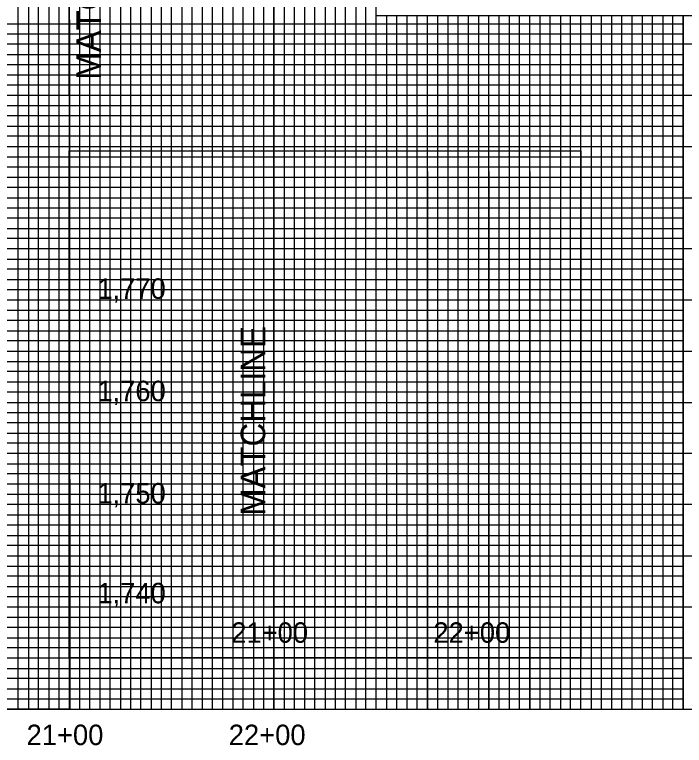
# Model space of a CAD drawing. Extents: x 505602 to 507548, y 483109 to 484209.
# Drawn here: x 506892.4 to 507219.7, y 483666.1 to 484023.2 of the extents above; entities that cross this region are included whole.
import ezdxf

# ---------------------------------------------------------------- set-up
doc = ezdxf.new("R2010")
doc.units = 0
for name, color, linetype in [('Exist Vertical Profile Vertical Axis Label', 7, 'Continuous'), ('Matchline', 7, 'Continuous'), ('Matchline Text', 7, 'Continuous'), ('Scratch_Level_5', 7, 'Continuous'), ('Sheet Layout Profile Border Port 1', 7, 'Continuous'), ('Sheet Profile CELL', 7, 'Continuous'), ('Sheet Profile Grid Major CELL', 7, 'Continuous'), ('Sheet Profile Grid Middle CELL', 7, 'Continuous'), ('Sheet Profile Grid Minor CELL', 7, 'Continuous'), ('Sheet Sticker Exception Certification CELL', 7, 'Continuous')]:
    doc.layers.add(name, color=color, linetype=linetype)

msp = doc.modelspace()

# ---------------------------------------------------------------- linework, layer by layer
at = {"layer": 'Matchline'}
for p, q in [((506919.08, 483983.71), (506919.08, 484183.71)), ((507019.08, 483750.46), (507019.08, 483883.71))]:
    msp.add_line(p, q, dxfattribs=at)
msp.add_lwpolyline([(506919.08, 483956.69), (507169.08, 483956.69), (507169.08, 483708.84), (506919.08, 483708.84)], close=True, dxfattribs=at)
at = {"layer": 'Scratch_Level_5'}
for points in [[(505819.08, 484183.83), (506824.84, 484183.83), (506824.84, 484134), (506919.08, 484133.22), (506919.3, 483683.71), (505819.08, 483683.71)], [(507019.08, 483883.71), (506919.08, 483883.71), (506919.08, 483956.69), (507119.08, 483956.69), (507119.08, 483733.71), (507019.08, 483733.71)]]:
    msp.add_lwpolyline(points, close=True, dxfattribs=at)
msp.add_lwpolyline([(505819.08, 484022.66), (505819.08, 483683.71), (507219.08, 483683.71), (507219.08, 484022.66)], dxfattribs=at)
at = {"layer": 'Sheet Layout Profile Border Port 1'}
msp.add_lwpolyline([(505819.08, 484185.09), (505819.08, 483683.71), (507019.08, 483683.71), (507019.08, 484183.71), (507019.08, 484183.71), (507019.08, 484183.71)], close=True, dxfattribs=at)
at = {"layer": 'Sheet Profile CELL'}
msp.add_line((505769.08, 483683.71), (507269.08, 483683.71), dxfattribs=at)
at = {"layer": 'Sheet Profile Grid Major CELL'}
for points in [[(506519.08, 483683.71), (506569.08, 483683.71), (506569.08, 484183.71), (506619.08, 484183.71), (506619.08, 483683.71), (506669.08, 483683.71), (506669.08, 484183.71), (506719.08, 484183.71), (506719.08, 483683.71), (506769.08, 483683.71), (506769.08, 484183.71), (506819.08, 484183.71), (506819.08, 483683.71), (506869.08, 483683.71), (506869.08, 484183.71), (506919.08, 484183.71), (506919.08, 483683.71), (506969.08, 483683.71), (506969.08, 484183.71), (507019.08, 484183.71), (507019.08, 483683.71), (507069.08, 483683.71), (507069.08, 484183.71), (507095.38, 484183.71)], [(507219.08, 484022.66), (507219.08, 483683.71), (507269.08, 483683.71), (507269.08, 484033.71)], [(507119.08, 484022.66), (507119.08, 483683.71), (507169.08, 483683.71), (507169.08, 483683.71), (507169.08, 484022.66)], [(507269.08, 483983.71), (505769.08, 483983.71), (505769.08, 483933.71), (507269.08, 483933.71)], [(507269.08, 483883.71), (505769.08, 483883.71), (505769.08, 483833.71), (507269.08, 483833.71)], [(507269.08, 483783.71), (505769.08, 483783.71), (505769.08, 483783.71), (505769.08, 483733.71), (507269.08, 483733.71)]]:
    msp.add_lwpolyline(points, dxfattribs=at)
at = {"layer": 'Sheet Profile Grid Middle CELL'}
for points in [[(506544.08, 483683.71), (506594.08, 483683.71), (506594.08, 484183.71), (506644.08, 484183.71), (506644.08, 483683.71), (506694.08, 483683.71), (506694.08, 484183.71), (506744.08, 484183.71), (506744.08, 483683.71), (506794.08, 483683.71), (506794.08, 484183.71), (506844.08, 484183.71), (506844.08, 483683.71), (506894.08, 483683.71), (506894.08, 484183.71), (506944.08, 484183.71), (506944.08, 483683.71), (506994.08, 483683.71), (506994.08, 484183.71), (507044.08, 484183.71), (507044.08, 483683.71), (507094.08, 483683.71), (507094.08, 484022.66)], [(507094.08, 483946.51), (507094.08, 483683.71), (507144.08, 483683.71), (507144.08, 484022.66)], [(507144.08, 483946.51), (507144.08, 483683.71), (507194.08, 483683.71), (507194.08, 484022.66)], [(507269.08, 484008.71), (505769.08, 484008.71), (505769.08, 483958.71), (507094.08, 483958.71)], [(507094.08, 483958.71), (507269.08, 483958.71)], [(507269.08, 483908.71), (505769.08, 483908.71), (505769.08, 483858.71), (507269.08, 483858.71)], [(507269.08, 483808.71), (505769.08, 483808.71), (505769.08, 483758.71), (507269.08, 483758.71)], [(507269.08, 483708.71), (505769.08, 483708.71)]]:
    msp.add_lwpolyline(points, dxfattribs=at)
at = {"layer": 'Sheet Profile Grid Minor CELL'}
for p, q in [((505819.08, 484018.71), (507219.08, 484018.71)), ((507219.08, 483998.71), (505819.08, 483998.71)), ((505819.08, 483993.71), (507219.08, 483993.71)), ((507219.08, 483973.71), (505819.08, 483973.71)), ((505819.08, 483968.71), (507219.08, 483968.71)), ((507219.08, 483948.71), (505819.08, 483948.71)), ((505819.08, 483943.71), (507219.08, 483943.71)), ((507219.08, 483938.71), (505819.08, 483938.71)), ((505819.08, 483928.71), (507219.08, 483928.71)), ((507219.08, 483923.71), (505819.08, 483923.71)), ((505819.08, 483918.71), (507219.08, 483918.71)), ((507219.08, 483913.71), (505819.08, 483913.71)), ((505819.08, 483903.71), (507219.08, 483903.71)), ((507219.08, 483898.71), (505819.08, 483898.71)), ((505819.08, 483893.71), (507219.08, 483893.71)), ((507219.08, 483888.71), (505819.08, 483888.71)), ((505819.08, 483878.71), (507219.08, 483878.71)), ((507219.08, 483873.71), (505819.08, 483873.71)), ((505819.08, 483868.71), (507219.08, 483868.71)), ((507219.08, 483863.71), (505819.08, 483863.71)), ((505819.08, 483853.71), (507219.08, 483853.71)), ((507219.08, 483848.71), (505819.08, 483848.71)), ((505819.08, 483843.71), (507219.08, 483843.71)), ((507219.08, 483838.71), (505819.08, 483838.71)), ((505819.08, 483828.71), (507219.08, 483828.71)), ((507219.08, 483823.71), (505819.08, 483823.71)), ((505819.08, 483818.71), (507219.08, 483818.71)), ((507219.08, 483813.71), (505819.08, 483813.71)), ((505819.08, 483803.71), (507219.08, 483803.71)), ((507219.08, 483798.71), (505819.08, 483798.71)), ((507219.08, 483793.71), (505819.08, 483793.71)), ((507219.08, 483788.71), (505819.08, 483788.71)), ((505819.08, 483778.71), (507219.08, 483778.71)), ((507219.08, 483773.71), (505819.08, 483773.71)), ((505819.08, 483768.71), (507219.08, 483768.71)), ((507219.08, 483763.71), (505819.08, 483763.71)), ((505819.08, 483753.71), (507219.08, 483753.71)), ((507219.08, 483748.71), (505819.08, 483748.71)), ((505819.08, 483743.71), (507219.08, 483743.71)), ((507219.08, 483738.71), (505819.08, 483738.71)), ((505819.08, 483728.71), (507219.08, 483728.71)), ((507219.08, 483723.71), (505819.08, 483723.71)), ((505819.08, 483718.71), (507219.08, 483718.71)), ((507219.08, 483713.71), (505819.08, 483713.71)), ((505819.08, 483703.71), (507219.08, 483703.71)), ((507219.08, 483698.71), (505819.08, 483698.71)), ((505819.08, 483693.71), (507219.08, 483693.71))]:
    msp.add_line(p, q, dxfattribs=at)
for points in [[(506889.08, 484183.71), (506899.08, 484183.71), (506899.08, 483683.71), (506904.08, 483683.71), (506904.08, 484183.71), (506909.08, 484183.71), (506909.08, 483683.71), (506914.08, 483683.71), (506914.08, 484183.71), (506924.08, 484183.71), (506924.08, 483683.71), (506929.08, 483683.71), (506929.08, 484183.71), (506934.08, 484183.71), (506934.08, 483683.71), (506939.08, 483683.71), (506939.08, 484183.71), (506949.08, 484183.71), (506949.08, 483683.71), (506954.08, 483683.71), (506954.08, 484183.71), (506959.08, 484183.71), (506959.08, 483683.71)], [(506959.08, 483683.71), (506964.08, 483683.71), (506964.08, 484183.71)], [(506974.08, 484183.71), (506974.08, 483683.71), (506979.08, 483683.71), (506979.08, 484183.71)], [(506984.08, 484183.71), (506984.08, 483683.71), (506989.08, 483683.71), (506989.08, 484183.71)], [(506999.08, 484183.71), (506999.08, 483683.71), (507004.08, 483683.71), (507004.08, 484183.71)], [(507009.08, 484183.71), (507009.08, 483683.71), (507014.08, 483683.71), (507014.08, 484183.71)], [(507024.08, 484183.71), (507024.08, 483683.71), (507029.08, 483683.71), (507029.08, 484183.71)], [(507034.08, 484183.71), (507034.08, 483683.71), (507039.08, 483683.71), (507039.08, 484183.71)], [(507049.08, 484183.71), (507049.08, 483683.71), (507054.08, 483683.71), (507054.08, 484183.71)], [(507059.08, 484183.71), (507059.08, 483683.71), (507064.08, 483683.71), (507064.08, 484183.71)], [(507074.08, 484022.66), (507074.08, 483683.71), (507079.08, 483683.71), (507079.08, 484022.66)], [(507084.08, 484022.66), (507084.08, 483683.71), (507089.08, 483683.71), (507089.08, 484022.66)], [(507099.08, 484022.66), (507099.08, 483683.71), (507099.08, 483683.71), (507104.08, 483683.71), (507109.08, 483683.71), (507109.08, 484022.66)], [(507104.08, 484022.66), (507104.08, 483683.71)], [(507114.07, 484022.66), (507113.98, 483683.76), (507118.98, 483683.76), (507124.08, 483683.71), (507124.08, 484022.66)], [(507124.08, 483946.51), (507124.08, 483683.71), (507129.08, 483683.71), (507129.08, 484022.66)], [(507134.08, 484022.66), (507134.08, 483683.71), (507139.08, 483683.71), (507139.08, 484022.66)], [(507149.08, 484022.66), (507149.08, 483683.71), (507154.08, 483683.71), (507154.08, 484022.66)], [(507159.08, 484022.66), (507159.08, 483683.71), (507164.08, 483683.71), (507164.08, 484022.66)], [(507174.08, 484022.66), (507174.08, 483683.71), (507179.08, 483683.71), (507179.08, 484022.66)], [(507184.08, 484022.66), (507184.08, 483683.71), (507189.08, 483683.71), (507189.08, 484022.66)], [(507199.08, 484022.66), (507199.08, 483683.71), (507204.08, 483683.71), (507204.08, 484022.66)], [(507209.08, 484022.66), (507209.08, 483683.71), (507214.08, 483683.71), (507214.08, 484022.66)], [(507219.08, 484013.71), (505819.08, 484013.71), (505819.08, 484003.71), (507219.08, 484003.71)], [(507219.08, 483988.71), (505819.08, 483988.71), (505819.08, 483978.71), (507219.08, 483978.71)], [(507219.08, 483963.71), (505819.08, 483963.71), (505819.08, 483953.71), (507219.08, 483953.71)], [(507219.08, 483688.71), (505819.08, 483688.71)]]:
    msp.add_lwpolyline(points, dxfattribs=at)
at = {"layer": 'Sheet Sticker Exception Certification CELL'}
for p, q in [((507069.03, 484022.66), (507069.03, 484046.16)), ((507069.03, 484022.66), (507069.03, 484046.16)), ((507269.07, 484022.66), (507069.03, 484022.66)), ((507269.07, 484022.66), (507069.03, 484022.66))]:
    msp.add_line(p, q, dxfattribs=at)

# ---------------------------------------------------------------- texts
at = {"layer": 'Exist Vertical Profile Vertical Axis Label'}
for s, p in [('1,770', (506932.78, 483884.28)), ('1,760', (506932.78, 483834.28)), ('1,750', (506932.78, 483784.28)), ('1,740', (506932.78, 483735.49)), ('21+00', (506998.21, 483716.21)), ('22+00', (507097.01, 483716.21)), ('21+00', (506898.21, 483666.21)), ('22+00', (506997.01, 483666.21))]:
    msp.add_text(s, height=10, dxfattribs=at).set_placement(p)
at = {"layer": 'Matchline Text'}
for p in [(506934.51, 483991.4), (507014.84, 483778.26)]:
    msp.add_text('MATCHLINE ', height=12, rotation=90, dxfattribs=at).set_placement(p)

doc.saveas('drawing.dxf')
